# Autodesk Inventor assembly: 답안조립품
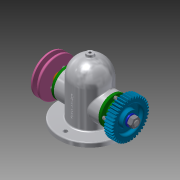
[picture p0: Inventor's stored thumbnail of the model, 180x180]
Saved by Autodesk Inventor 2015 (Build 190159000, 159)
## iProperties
Created: 2019-11
Part Number: 답안조립품
Document SubType Name: Assembly
Designer: now
Author: now
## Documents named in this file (14)
- C:\Users\now\Desktop\491104V1033\공용부품\답안조립품.iam
- C:\Users\now\Desktop\491104V1033\공용부품\V-벨트풀리.ipt
- V-벨트풀리.ipt
- C:\Users\now\Desktop\491104V1033\공용부품\너트 M12x1.25.ipt
- C:\Users\now\Desktop\491104V1033\공용부품\베어링 6203.ipt
- C:\Users\now\Desktop\491104V1033\공용부품\본체.ipt
- C:\Users\now\Desktop\491104V1033\공용부품\볼트 M4.ipt
- C:\Users\now\Desktop\491104V1033\공용부품\부시.ipt
- C:\Users\now\Desktop\491104V1033\공용부품\스퍼기어.ipt
- C:\Users\now\Desktop\491104V1033\공용부품\오일 실 26 38 8.ipt
- C:\Users\now\Desktop\491104V1033\공용부품\와셔 12x24.ipt
- C:\Users\now\Desktop\491104V1033\공용부품\축.ipt
- C:\Users\now\Desktop\491104V1033\공용부품\커버.ipt
- C:\Users\now\Desktop\491104V1033\공용부품\키 5x5x12.ipt
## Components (1 placed, 1 different names)
1. V-벨트풀리:1 — 각도:3
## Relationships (1: Angle 1)
- 각도:3 [Angle]: V-벨트풀리:1
